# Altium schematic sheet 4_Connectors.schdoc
size 309 x 223 mm; Symbol: Artery_A4; Device: Artery_A4; Company: Artery Technology; Drawed: SD; Version: 1.3; Page Size: A4; @Project Name: AT-START-A403A V1.3; @Page Count: 5; @Update Date: 2023-11-22; @Create Date: 2022-12-01; @Schematic Name: AT_START_A403A; @Page No: 4; @Page Name: Connectors
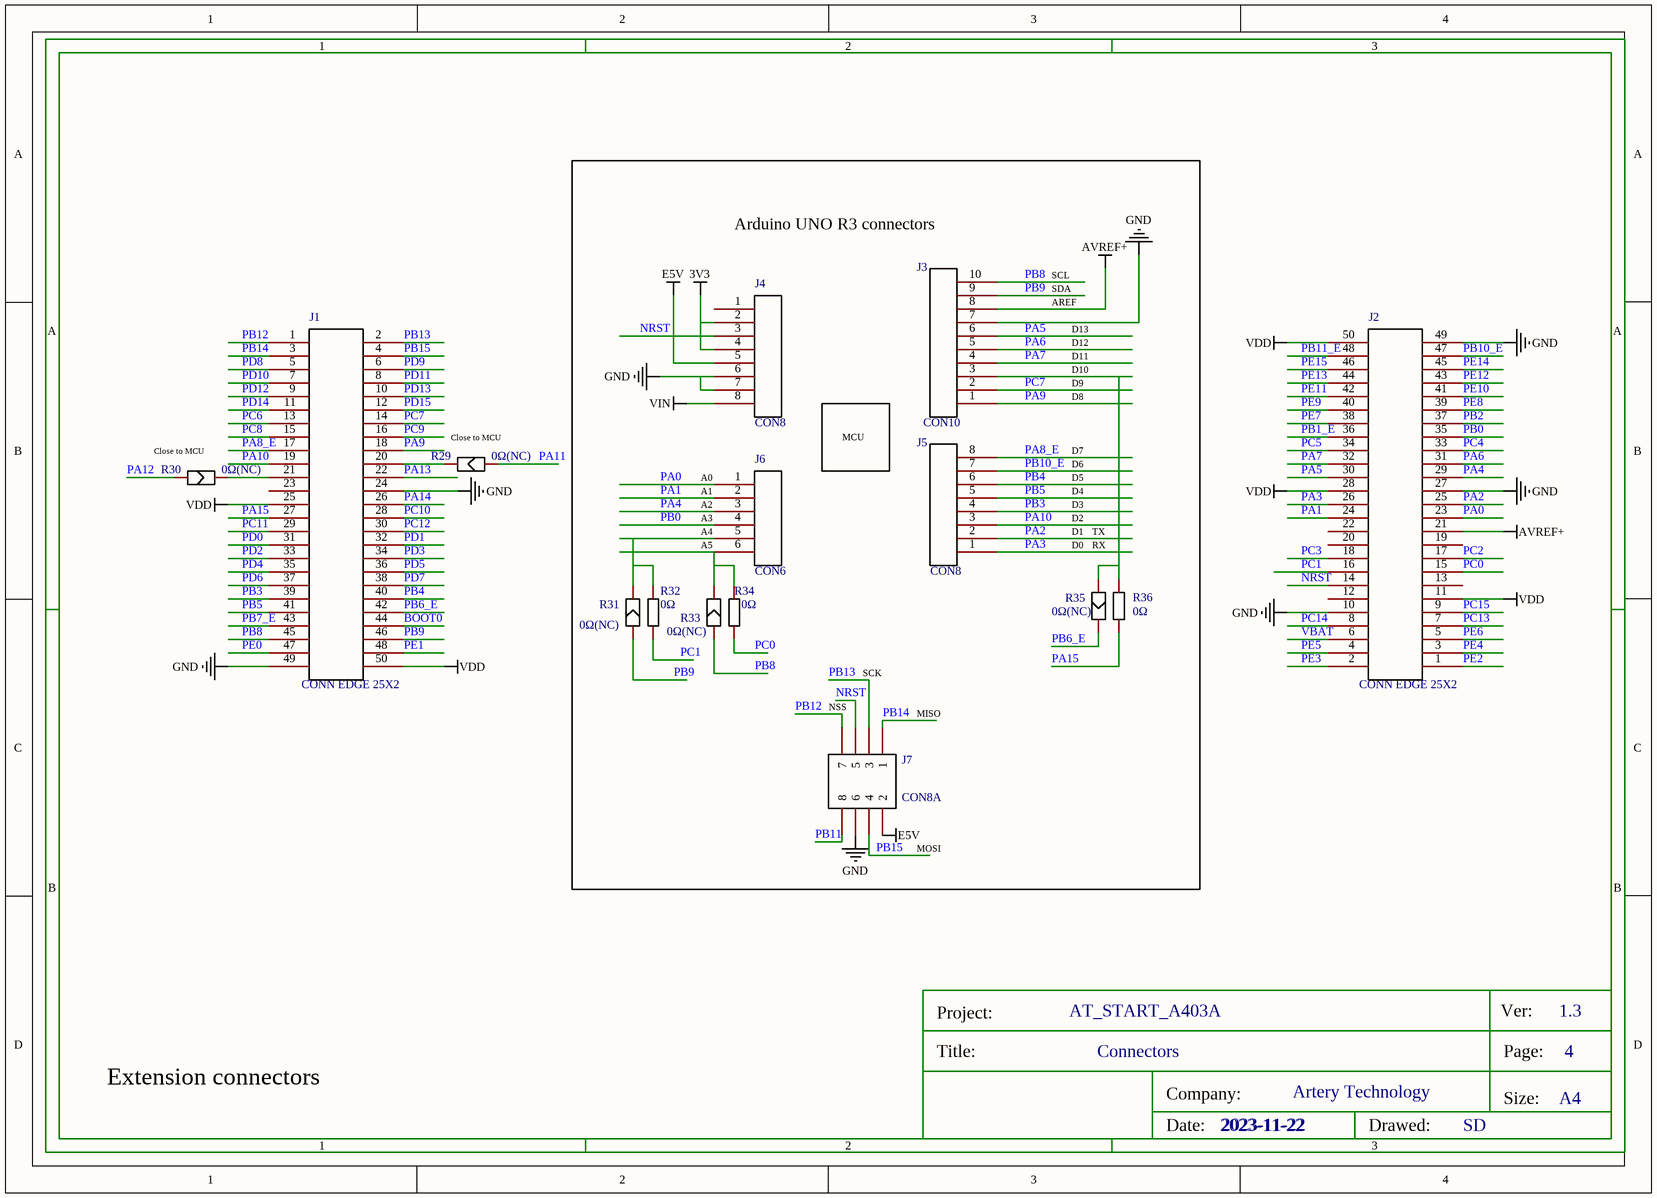
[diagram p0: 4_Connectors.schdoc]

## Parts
J1  CONN EDGE 25X2  [HEAD2*25]
J2  CONN EDGE 25X2  [HEAD2*25]
J3  CON10  [HDR1X10 - 2#]
J4  CON8  [HDR1X8 - 2#]
J5  CON8  [HDR1X8 - 2#]
J6  CON6  [HDR1X6 -2#]
J7  CON8A  [HDR2X4]
R29  value 0Ω(NC)  [SB-PAD]  (hidden comment: NC)
R30  value 0Ω(NC)  [SB-PAD]  (hidden comment: NC)
R31  value 0Ω(NC)  [SB-PAD]  (hidden comment: NC)
R32  value 0Ω  [R0603]  (hidden comment: 0603WAF0000T5E)
R33  value 0Ω(NC)  [SB-PAD]  (hidden comment: NC)
R34  value 0Ω  [R0603]  (hidden comment: 0603WAF0000T5E)
R35  value 0Ω(NC)  [SB-PAD]  (hidden comment: NC)
R36  value 0Ω  [R0603]  (hidden comment: 0603WAF0000T5E)

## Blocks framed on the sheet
Arduino UNO R3 connectors: J3-J7 R31-R36

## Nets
3V3: J4.2 J4.4
AVREF+: J2.21 J3.8
E5V: J4.5 J7.2
GND: J1.24 J1.49 J2.10 J2.27 J2.49 J3.7 J4.6 J4.7 J7.6
VDD: J1.25 J1.50 J2.11 J2.28 J2.50
VIN: J4.8
BOOT0: J1.44
NRST: J2.14 J4.3 J7.5
PA0: J2.23 J6.1
PA1: J2.24 J6.2
PA2: J2.25 J5.2
PA3: J2.26 J5.1
PA4: J2.29 J6.3
PA5: J2.30 J3.6
PA6: J2.31 J3.5
PA7: J2.32 J3.4
PA8_E: J1.17 J5.8
PA9: J1.18 J3.1
PA10: J1.19 J5.3
PA11: R29.1
PA12: R30.1
PA13: J1.22
PA14: J1.26
PA15: J1.27 R36.1
PB0: J2.35 J6.4
PB1_E: J2.36
PB2: J2.37
PB3: J1.39 J5.4
PB4: J1.40 J5.6
PB5: J1.41 J5.5
PB6_E: J1.42 R35.2
PB7_E: J1.43
PB8: J1.45 J3.10 R33.1
PB9: J1.46 J3.9 R31.1
PB10_E: J2.47 J5.7
PB11: J7.8
PB11_E: J2.48
PB12: J1.1 J7.7
PB13: J1.2 J7.3
PB14: J1.3 J7.1
PB15: J1.4 J7.4
PC0: J2.15 R34.2
PC1: J2.16 R32.2
PC2: J2.17
PC3: J2.18
PC4: J2.33
PC5: J2.34
PC6: J1.13
PC7: J1.14 J3.2
PC8: J1.15
PC9: J1.16
PC10: J1.28
PC11: J1.29
PC12: J1.30
PC13: J2.7
PC14: J2.8
PC15: J2.9
PD0: J1.31
PD1: J1.32
PD2: J1.33
PD3: J1.34
PD4: J1.35
PD5: J1.36
PD6: J1.37
PD7: J1.38
PD8: J1.5
PD9: J1.6
PD10: J1.7
PD11: J1.8
PD12: J1.9
PD13: J1.10
PD14: J1.11
PD15: J1.12
PE0: J1.47
PE1: J1.48
PE2: J2.1
PE3: J2.2
PE4: J2.3
PE5: J2.4
PE6: J2.5
PE7: J2.38
PE8: J2.39
PE9: J2.40
PE10: J2.41
PE11: J2.42
PE12: J2.43
PE13: J2.44
PE14: J2.45
PE15: J2.46
VBAT: J2.6
NetJ1_20: J1.20 R29.2
NetJ1_21: J1.21 R30.2
NetJ3_3: J3.3 R35.1 R36.2
NetJ6_5: J6.5 R31.2 R32.1
NetJ6_6: J6.6 R33.2 R34.1

Not connected (* = marked no-connect by the designer): J1 23; J2 12 13 19 20 22; J4 1

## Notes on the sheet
- SCL
- AREF
- SDA
- D13
- D8
- D9
- D10
- D11
- D12
- (near R30) Close to MCU
- (near R29) Close to MCU
- MCU
- D6
- D7
- (near J6) A0
- (near J6) A1
- (near J6) A2
- (near J6) A3
- A4
- A5
- D0
- D1
- D2
- D3
- D4
- D5
- TX
- RX
- SCK
- (near J7) NSS
- (near J7) MISO
- (near J7) MOSI
- Extension connectors
- 2023-11-22

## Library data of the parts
J1 J2 = CONN EDGE 25X2: Add into BOM: yes
J3 = CON10: Symbol: CON10_0; Add into BOM: yes
J4 J5 = CON8: Add into BOM: yes
J6 = CON6: Add into BOM: yes
J7 = CON8A: Header, 4-Pin, Dual row; Symbol: Header 4X2; Add into BOM: yes
R29-R31 R33 R35 = NC_SB-PAD: Convert to PCB: yes
R32 R34 R36 = 0603WAF0000T5E: 电阻类型:厚膜电阻;阻值:0Ω;精度:±1%;功率:100mW;最大工作电压:75V;工作温度范围:-55℃~+155℃;; Manufacturer: UNI-ROYAL(厚声); Add into BOM: yes; Tolerance: ±1%; Power(Watts): 100mW; Overload Voltage (Max): 75V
